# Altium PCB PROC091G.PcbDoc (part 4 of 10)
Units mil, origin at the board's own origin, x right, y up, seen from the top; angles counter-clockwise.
Board outline 4538.11 x 994.94 mil, 8 copper layers (Top Layer, GND1, Sig1, PWR1, PWR2, Sig2, GND2, Bottom Layer), stack 59.155 mil thick; 446 components, 329 nets, 5050 pads, 868 vias.
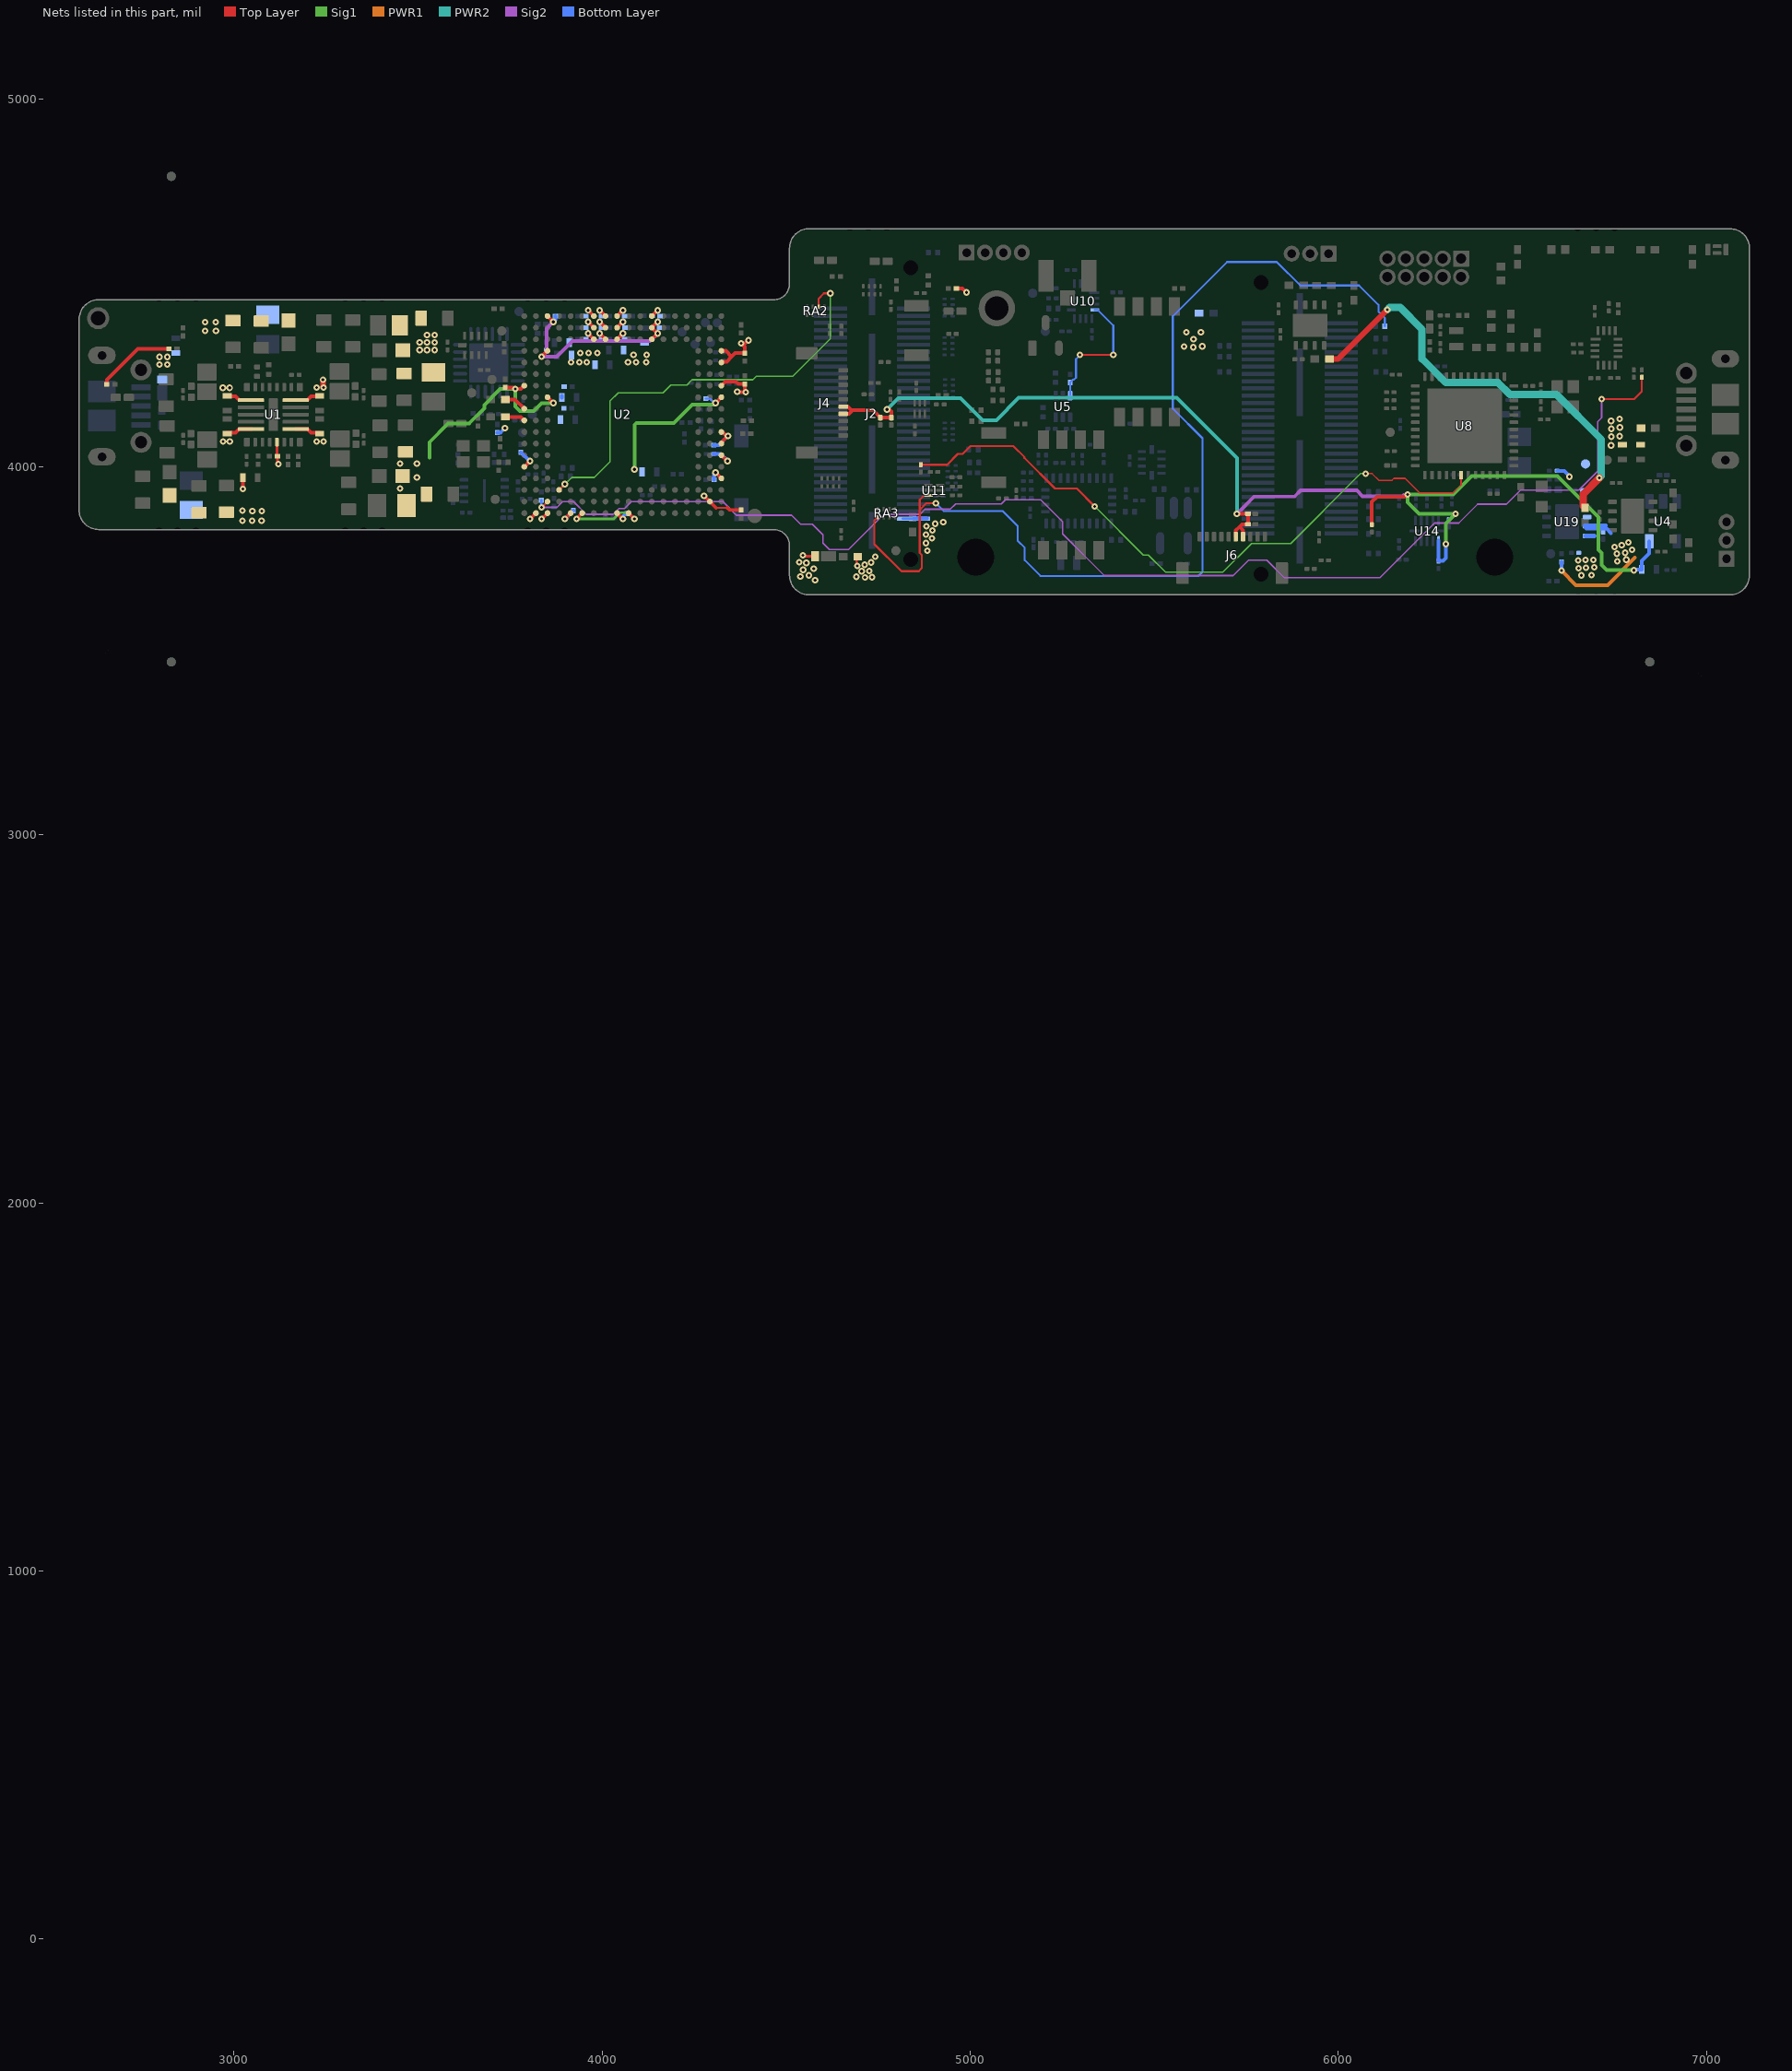
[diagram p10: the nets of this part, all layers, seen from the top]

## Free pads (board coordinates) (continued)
  round 7 on Mech16: 1(2948.71,736.96) 1(2948.71,736.96) 1(2948.71,777.96) 1(2948.71,777.96) 1(2971.71,736.96) 1(2971.71,777.96) 1(3021.71,736.96) 1(3021.71,777.96) 1(3044.71,736.96) 1(3044.71,736.96) 1(3044.71,777.96) 1(3044.71,777.96) 1(3078.65,310.39) 1(3078.65,310.39) 1(3078.65,410.39) 1(3078.65,510.39) 1(3078.65,510.39) 1(3178.65,310.39) 1(3178.65,410.39) 1(3178.65,410.39) 1(3227.52,1910.06) 1(3227.52,1910.06) 1(3227.52,1933.06) 1(3227.52,1983.06) 1(3227.52,2006.06) 1(3227.52,2006.06) 1(3228.65,88.39) 1(3228.65,88.39) 1(3228.65,188.39) 1(3228.65,288.39) 1(3228.65,288.39) 1(3252.65,1637.89) 1(3252.65,1637.89) 1(3252.65,1678.89) 1(3252.65,1678.89) 1(3253.27,1687.42) 1(3253.27,1687.42) 1(3253.27,1728.42) 1(3253.27,1728.42) 1(3253.91,1076.83) 1(3253.91,1076.83) 1(3253.91,1117.83) 1(3253.91,1117.83) 1(3253.91,1126.83) 1(3253.91,1126.83) 1(3253.91,1167.83) 1(3253.91,1167.83) 1(3253.91,1176.83) 1(3253.91,1176.83) 1(3253.91,1217.83) 1(3253.91,1217.83) 1(3253.91,1226.83) 1(3253.91,1226.83) 1(3253.91,1267.83) 1(3253.91,1267.83) 1(3253.91,1276.83) 1(3253.91,1276.83) 1(3253.91,1317.83) 1(3253.91,1317.83) 1(3253.91,1331.83) 1(3253.91,1331.83) 1(3253.91,1372.83) 1(3253.91,1372.83) 1(3253.91,1381.83) 1(3253.91,1381.83) 1(3253.91,1422.83) 1(3253.91,1422.83) 1(3253.91,1486.83) 1(3253.91,1486.83) 1(3253.91,1527.83) 1(3253.91,1527.83) 1(3253.91,1536.83) 1(3253.91,1536.83) 1(3253.91,1577.83) 1(3253.91,1577.83) 1(3253.91,1586.83) 1(3253.91,1586.83) 1(3253.91,1627.83) 1(3253.91,1627.83) 1(3253.91,1026.83) 1(3253.91,1026.83) 1(3253.91,1067.83) 1(3253.91,1067.83) 1(3253.91,1431.83) 1(3253.91,1431.83) 1(3253.91,1472.83) 1(3253.91,1472.83) 1(3268.52,1910.06) 1(3268.52,1910.06) 1(3268.52,1933.06) 1(3268.52,1983.06) 1(3268.52,2006.06) 1(3268.52,2006.06) 1(3275.65,1637.89) 1(3275.65,1678.89) 1(3276.27,1687.42) 1(3276.27,1728.42) 1(3276.91,1076.83) 1(3276.91,1117.83) 1(3276.91,1126.83) 1(3276.91,1167.83) 1(3276.91,1176.83) 1(3276.91,1217.83) 1(3276.91,1226.83) 1(3276.91,1267.83) 1(3276.91,1276.83) 1(3276.91,1317.83) 1(3276.91,1331.83) 1(3276.91,1372.83) 1(3276.91,1381.83) 1(3276.91,1422.83) 1(3276.91,1486.83) 1(3276.91,1527.83) 1(3276.91,1536.83) 1(3276.91,1577.83) 1(3276.91,1586.83) 1(3276.91,1627.83) 1(3276.91,1026.83) 1(3276.91,1067.83) 1(3276.91,1431.83) 1(3276.91,1472.83) 1(3296.75,1733.96) 1(3296.75,1733.96) 1(3296.75,1759.94) 1(3296.75,1827.94) 1(3296.75,1853.92) 1(3296.75,1853.92) 1(3297.01,1910.44) 1(3297.01,1910.44) 1(3297.01,1933.44) 1(3297.01,1983.44) 1(3297.01,2006.44) 1(3297.01,2006.44) 1(3316.37,680.35) 1(3316.37,680.35) 1(3316.37,734.81) 1(3316.37,734.81) 1(3325.65,1637.89) 1(3325.65,1678.89) 1(3326.27,1687.42) 1(3326.27,1728.42) 1(3326.91,1076.83) 1(3326.91,1117.83) 1(3326.91,1126.83) 1(3326.91,1167.83) 1(3326.91,1176.83) 1(3326.91,1217.83) 1(3326.91,1226.83) 1(3326.91,1267.83) 1(3326.91,1276.83) 1(3326.91,1317.83) 1(3326.91,1331.83) 1(3326.91,1372.83) 1(3326.91,1381.83) 1(3326.91,1422.83) 1(3326.91,1486.83) 1(3326.91,1527.83) 1(3326.91,1536.83) 1(3326.91,1577.83) 1(3326.91,1586.83) 1(3326.91,1627.83) 1(3326.91,1026.83) 1(3326.91,1067.83) 1(3326.91,1431.83) 1(3326.91,1472.83) 1(3328.65,88.39) 1(3328.65,188.39) 1(3328.65,188.39) 1(3338.01,1910.44) 1(3338.01,1910.44) 1(3338.01,1933.44) 1(3338.01,1983.44) 1(3338.01,2006.44) 1(3338.01,2006.44) 1(3342.35,680.35) 1(3342.35,734.81) 1(3348.65,1637.89) 1(3348.65,1637.89) 1(3348.65,1678.89) 1(3348.65,1678.89) 1(3349.27,1687.42) 1(3349.27,1687.42) 1(3349.27,1728.42) 1(3349.27,1728.42) 1(3349.91,1076.83) 1(3349.91,1076.83) 1(3349.91,1117.83) 1(3349.91,1117.83) 1(3349.91,1126.83) 1(3349.91,1126.83) 1(3349.91,1167.83) 1(3349.91,1167.83) 1(3349.91,1176.83) 1(3349.91,1176.83) 1(3349.91,1217.83) 1(3349.91,1217.83) 1(3349.91,1226.83) 1(3349.91,1226.83) 1(3349.91,1267.83) 1(3349.91,1267.83) 1(3349.91,1276.83) 1(3349.91,1276.83) 1(3349.91,1317.83) 1(3349.91,1317.83) 1(3349.91,1331.83) 1(3349.91,1331.83) 1(3349.91,1372.83) 1(3349.91,1372.83) 1(3349.91,1381.83) 1(3349.91,1381.83) 1(3349.91,1422.83) 1(3349.91,1422.83) 1(3349.91,1486.83) 1(3349.91,1486.83) 1(3349.91,1527.83) 1(3349.91,1527.83) 1(3349.91,1536.83) 1(3349.91,1536.83) 1(3349.91,1577.83) 1(3349.91,1577.83) 1(3349.91,1586.83) 1(3349.91,1586.83) 1(3349.91,1627.83) 1(3349.91,1627.83) 1(3349.91,1026.83) 1(3349.91,1026.83) 1(3349.91,1067.83) 1(3349.91,1067.83) 1(3349.91,1431.83) 1(3349.91,1431.83) 1(3349.91,1472.83) 1(3349.91,1472.83) 1(3351.22,1733.96) 1(3351.22,1733.96) 1(3351.22,1759.94) 1(3351.22,1827.94) 1(3351.22,1853.92) 1(3351.22,1853.92) 1(3389.82,1421.46) 1(3389.82,1421.46) 1(3389.82,1447.44) 1(3389.82,1515.44) 1(3389.82,1541.42) 1(3389.82,1541.42) 1(3410.35,680.35) 1(3410.35,734.81) 1(3436.33,680.35) 1(3436.33,680.35) 1(3436.33,734.81) 1(3436.33,734.81) 1(3444.28,1421.46) 1(3444.28,1421.46) 1(3444.28,1447.44) 1(3444.28,1515.44) 1(3444.28,1541.42) 1(3444.28,1541.42) 1(3453.4,2001.94) 1(3453.4,2001.94) 1(3453.4,2042.94) 1(3453.4,2042.94) 1(3454.02,1923.94) 1(3454.02,1923.94) 1(3454.02,1964.94) 1(3454.02,1964.94) 1(3476.4,2001.94) 1(3476.4,2042.94) 1(3477.02,1923.94) 1(3477.02,1964.94) 1(3511.28,2264.89) 1(3511.28,2264.89) 1(3511.28,2305.89) 1(3511.28,2305.89) 1(3518.76,1756.44) 1(3518.76,1756.44) 1(3518.76,1779.44) 1(3518.76,1829.44) 1(3518.76,1852.44) 1(3518.76,1852.44) 1(3526.4,2001.94) 1(3526.4,2042.94) 1(3527.02,1923.94) 1(3527.02,1964.94) 1(3531.97,2113.83) 1(3531.97,2113.83) 1(3531.97,2154.83) 1(3531.97,2154.83) 1(3534.28,2264.89) 1(3534.28,2305.89) 1(3549.4,2001.94) 1(3549.4,2001.94) 1(3549.4,2042.94) 1(3549.4,2042.94) 1(3550.02,1923.94) 1(3550.02,1923.94) 1(3550.02,1964.94) 1(3550.02,1964.94) 1(3554.97,2113.83) 1(3554.97,2154.83) 1(3559.76,1756.44) 1(3559.76,1756.44) 1(3559.76,1779.44) 1(3559.76,1829.44) 1(3559.76,1852.44) 1(3559.76,1852.44) 1(3584.28,2264.89) 1(3584.28,2305.89) 1(3586.87,2535.95) 1(3586.87,2535.95) 1(3586.87,2561.93) 1(3586.87,2629.93) 1(3586.87,2655.91) 1(3586.87,2655.91) 1(3587.52,1796.44) 1(3587.52,1796.44) 1(3587.52,1819.44) 1(3587.52,1869.44) 1(3587.52,1892.44) 1(3587.52,1892.44) 1(3604.97,2113.83) 1(3604.97,2154.83) 1(3607.28,2264.89) 1(3607.28,2264.89) 1(3607.28,2305.89) 1(3607.28,2305.89) 1(3627.97,2113.83) 1(3627.97,2113.83) 1(3627.97,2154.83) 1(3627.97,2154.83) 1(3628.52,1796.44) 1(3628.52,1796.44) 1(3628.52,1819.44) 1(3628.52,1869.44) 1(3628.52,1892.44) 1(3628.52,1892.44) 1(3641.33,2535.95) 1(3641.33,2535.95) 1(3641.33,2561.93) 1(3641.33,2629.93) 1(3641.33,2655.91) 1(3641.33,2655.91) 1(3660.65,2692.89) 1(3660.65,2692.89) 1(3660.65,2733.89) 1(3660.65,2733.89) 1(3683.65,2692.89) 1(3683.65,2733.89) 1(3685.16,2766.12) 1(3685.16,2766.12) 1(3685.16,2820.59) 1(3685.16,2820.59) 1(3700.65,2832.89) 1(3700.65,2832.89) 1(3700.65,2873.89) 1(3700.65,2873.89) 1(3702.5,2882.04) 1(3702.5,2882.04) 1(3702.5,2923.04) 1(3702.5,2923.04) 1(3702.5,2932.04) 1(3702.5,2932.04) 1(3702.5,2973.04) 1(3702.5,2973.04) 1(3702.5,2982.04) 1(3702.5,2982.04) 1(3702.5,3023.04) 1(3702.5,3023.04) 1(3702.5,3082.04) 1(3702.5,3082.04) 1(3702.5,3123.04) 1(3702.5,3123.04) 1(3705.65,3132.89) 1(3705.65,3132.89) 1(3705.65,3173.89) 1(3705.65,3173.89) 1(3705.65,3187.89) 1(3705.65,3187.89) 1(3705.65,3228.89) 1(3705.65,3228.89) 1(3711.14,2766.12) 1(3711.14,2820.59) 1(3723.65,2832.89) 1(3723.65,2873.89) 1(3725.5,2882.04) 1(3725.5,2923.04) 1(3725.5,2932.04) 1(3725.5,2973.04) 1(3725.5,2982.04) 1(3725.5,3023.04) 1(3725.5,3082.04) 1(3725.5,3123.04) 1(3727.02,1435.44) 1(3727.02,1435.44) 1(3727.02,1469.44) 1(3727.02,1549.44) 1(3727.02,1583.44) 1(3727.02,1583.44) 1(3728.65,88.39) 1(3728.65,88.39) 1(3728.65,288.39) 1(3728.65,288.39) 1(3728.65,3132.89) 1(3728.65,3173.89) 1(3728.65,3187.89) 1(3728.65,3228.89) 1(3733.65,2692.89) 1(3733.65,2733.89) 1(3745.29,729.24) 1(3745.29,729.24) 1(3745.29,760.95) 1(3745.29,879.93) 1(3745.29,911.64) 1(3745.29,911.64) 1(3756.65,2692.89) 1(3756.65,2692.89) 1(3756.65,2733.89) 1(3756.65,2733.89) 1(3767.02,1435.44) 1(3767.02,1435.44) 1(3767.02,1583.44) 1(3767.02,1583.44) 1(3770.53,1331.8) 1(3770.53,1331.8) 1(3770.53,1427.08) 1(3770.53,1427.08) 1(3773.02,3354.94) 1(3773.02,3354.94) 1(3773.02,3395.94) 1(3773.02,3395.94) 1(3773.65,2832.89) 1(3773.65,2873.89) 1(3775.5,2882.04) 1(3775.5,2923.04) 1(3775.5,2932.04) 1(3775.5,2973.04) 1(3775.5,2982.04) 1(3775.5,3023.04) 1(3775.5,3082.04) 1(3775.5,3123.04) 1(3778.65,3132.89) 1(3778.65,3173.89) 1(3778.65,3187.89) 1(3778.65,3228.89) 1(3779.14,2766.12) 1(3779.14,2820.59) 1(3780.01,1116.9) 1(3780.01,1116.9) 1(3780.01,1152.33) 1(3780.01,1270.44) 1(3780.01,1305.87) 1(3780.01,1305.87) 1(3796.02,3354.94) 1(3796.02,3395.94) 1(3796.65,2832.89) 1(3796.65,2832.89) 1(3796.65,2873.89) 1(3796.65,2873.89) 1(3798.5,2882.04) 1(3798.5,2882.04) 1(3798.5,2923.04) 1(3798.5,2923.04) 1(3798.5,2932.04) 1(3798.5,2932.04) 1(3798.5,2973.04) 1(3798.5,2973.04) 1(3798.5,2982.04) 1(3798.5,2982.04) 1(3798.5,3023.04) 1(3798.5,3023.04) 1(3798.5,3082.04) 1(3798.5,3082.04) 1(3798.5,3123.04) 1(3798.5,3123.04) 1(3801.65,3132.89) 1(3801.65,3132.89) 1(3801.65,3173.89) 1(3801.65,3173.89) 1(3801.65,3187.89) 1(3801.65,3187.89) 1(3801.65,3228.89) 1(3801.65,3228.89) 1(3805.13,2766.12) 1(3805.13,2766.12) 1(3805.13,2820.59) 1(3805.13,2820.59) 1(3805.96,1331.8) 1(3805.96,1427.08) 1(3807.02,1435.44) 1(3807.02,1435.44) 1(3807.02,1469.44) 1(3807.02,1549.44) 1(3807.02,1583.44) 1(3807.02,1583.44) 1(3809.81,931.38) 1(3809.81,931.38) 1(3809.81,971.38) 1(3809.81,971.38) 1(3809.81,1011.38) 1(3809.81,1011.38) 1(3820.79,1542.03) 1(3820.79,1542.03) 1(3820.79,1596.5) 1(3820.79,1596.5) 1(3831.38,2523.4) 1(3831.38,2523.4) 1(3831.38,2549.39) 1(3831.38,2617.39) 1(3831.38,2643.37) 1(3831.38,2643.37) 1(3833.14,2408.52) 1(3833.14,2408.52) 1(3833.14,2484.02) 1(3833.14,2484.02) 1(3833.83,2407.82) 1(3833.83,2407.82) 1(3843.81,931.38) 1(3843.81,1011.38) 1(3846.02,3354.94) 1(3846.02,3395.94) 1(3846.45,2653.4) 1(3846.45,2653.4) 1(3846.45,2679.39) 1(3846.45,2747.39) 1(3846.45,2773.37) 1(3846.45,2773.37) 1(3846.78,1542.03) 1(3846.78,1596.5) 1(3868.74,729.24) 1(3868.74,729.24) 1(3868.74,760.95) 1(3868.74,879.93) 1(3868.74,911.64) 1(3868.74,911.64) 1(3869.02,3354.94) 1(3869.02,3354.94) 1(3869.02,3395.94) 1(3869.02,3395.94) 1(3870.74,2407.82) 1(3870.74,2484.02) 1(3875.29,1116.9) 1(3875.29,1116.9) 1(3875.29,1152.33) 1(3875.29,1270.44) 1(3875.29,1305.87) 1(3875.29,1305.87) 1(3878.02,759.44) 1(3878.02,759.44) 1(3878.02,793.44) 1(3878.02,873.44) 1(3878.02,907.44) 1(3878.02,907.44) 1(3878.65,310.39) 1(3878.65,310.39) 1(3878.65,510.39) 1(3878.65,510.39) 1(3885.85,2523.4) 1(3885.85,2523.4) 1(3885.85,2549.39) 1(3885.85,2617.39) 1(3885.85,2643.37) 1(3885.85,2643.37) 1(3893.65,310.39) 1(3893.65,310.39) 1(3893.65,410.39) 1(3893.65,510.39) 1(3893.65,510.39) 1(3900.91,2653.4) 1(3900.91,2653.4) 1(3900.91,2679.39) 1(3900.91,2747.39) 1(3900.91,2773.37) 1(3900.91,2773.37) 1(3910.02,2502.94) 1(3910.02,2502.94) 1(3910.02,2543.94) 1(3910.02,2543.94) 1(3910.93,2615.57) 1(3910.93,2615.57) 1(3910.93,2638.57) 1(3910.93,2688.57) 1(3910.93,2711.57) 1(3910.93,2711.57) 1(3911.02,1273.94) 1(3911.02,1273.94) 1(3911.02,1314.94) 1(3911.02,1314.94) 1(3914.78,1542.03) 1(3914.78,1596.5) 1(3914.81,2752.07) 1(3914.81,2752.07) 1(3914.81,2793.07) 1(3914.81,2793.07) 1(3915.93,3359.57) 1(3915.93,3359.57) 1(3915.93,3382.57) 1(3915.93,3432.57) 1(3915.93,3455.57) 1(3915.93,3455.57) 1(3918.02,759.44) 1(3918.02,759.44) 1(3918.02,907.44) 1(3918.02,907.44) 1(3923.81,931.38) 1(3923.81,1011.38) 1(3924.07,1331.8) 1(3924.07,1427.08) 1(3930.74,2407.82) 1(3930.74,2484.02) 1(3933.02,2502.94) 1(3933.02,2543.94) 1(3934.02,1273.94) 1(3934.02,1314.94) 1(3937.81,2752.07) 1(3937.81,2793.07) 1(3940.76,1542.03) 1(3940.76,1542.03) 1(3940.76,1596.5) 1(3940.76,1596.5) 1(3951.93,2615.57) 1(3951.93,2615.57) 1(3951.93,2638.57) 1(3951.93,2688.57) 1(3951.93,2711.57) 1(3951.93,2711.57) 1(3956.93,3359.57) 1(3956.93,3359.57) 1(3956.93,3382.57) 1(3956.93,3432.57) 1(3956.93,3455.57) 1(3956.93,3455.57) 1(3957.81,931.38) 1(3957.81,931.38) 1(3957.81,971.38) 1(3957.81,971.38) 1(3957.81,1011.38) 1(3957.81,1011.38) 1(3958.02,759.44) 1(3958.02,759.44) 1(3958.02,793.44) 1(3958.02,873.44) 1(3958.02,907.44) 1(3958.02,907.44) 1(3959.51,1331.8) 1(3959.51,1331.8) 1(3959.51,1427.08) 1(3959.51,1427.08) 1(3962.08,2615.57) 1(3962.08,2615.57) 1(3962.08,2638.57) 1(3962.08,2688.57) 1(3962.08,2711.57) 1(3962.08,2711.57) 1(3965.93,3359.57) 1(3965.93,3359.57) 1(3965.93,3382.57) 1(3965.93,3432.57) 1(3965.93,3455.57) 1(3965.93,3455.57) 1(3967.64,2407.82) 1(3967.64,2407.82) 1(3968.34,2408.52) 1(3968.34,2408.52) 1(3968.34,2484.02) 1(3968.34,2484.02) 1(3969.54,586.85) 1(3969.54,586.85) 1(3969.54,608.11) 1(3969.54,698.66) 1(3969.54,719.92) 1(3969.54,719.92) 1(3983.02,2502.94) 1(3983.02,2543.94) 1(3983.15,2376.76) 1(3983.15,2376.76) 1(3983.15,2399.76) 1(3983.15,2449.76) 1(3983.15,2472.76) 1(3983.15,2472.76) 1(3984.02,1273.94) 1(3984.02,1314.94) 1(3987.81,2752.07) 1(3987.81,2793.07) 1(3993.65,310.39) 1(3993.65,410.39) 1(3993.65,410.39) 1(4003.08,2615.57) 1(4003.08,2615.57) 1(4003.08,2638.57) 1(4003.08,2688.57) 1(4003.08,2711.57) 1(4003.08,2711.57) 1(4006.02,2502.94) 1(4006.02,2502.94) 1(4006.02,2543.94) 1(4006.02,2543.94) 1(4006.93,3359.57) 1(4006.93,3359.57) 1(4006.93,3382.57) 1(4006.93,3432.57) 1(4006.93,3455.57) 1(4006.93,3455.57) 1(4007.02,1273.94) 1(4007.02,1273.94) 1(4007.02,1314.94) 1(4007.02,1314.94) 1(4010.81,2752.07) 1(4010.81,2752.07) 1(4010.81,2793.07) 1(4010.81,2793.07) 1(4011.27,545.12) 1(4011.27,545.12) 1(4011.27,761.65) 1(4011.27,761.65) 1(4012.08,2615.57) 1(4012.08,2615.57) 1(4012.08,2638.57) 1(4012.08,2688.57) 1(4012.08,2711.57) 1(4012.08,2711.57) 1(4015.93,3359.57) 1(4015.93,3359.57) 1(4015.93,3382.57) 1(4015.93,3432.57) 1(4015.93,3455.57) 1(4015.93,3455.57) 1(4024.15,2376.76) 1(4024.15,2376.76) 1(4024.15,2399.76) 1(4024.15,2449.76) 1(4024.15,2472.76) 1(4024.15,2472.76) 1(4025.15,1282.63) 1(4025.15,1306.25) 1(4036.02,2250.94) 1(4036.02,2250.94) 1(4036.02,2291.94) 1(4036.02,2291.94) 1(4053.08,2615.57) 1(4053.08,2615.57) 1(4053.08,2638.57) 1(4053.08,2688.57) 1(4053.08,2711.57) 1(4053.08,2711.57) 1(4055.93,3464.57) 1(4055.93,3464.57) 1(4055.93,3487.57) 1(4055.93,3537.57) 1(4055.93,3560.57) 1(4055.93,3560.57) 1(4056.93,3359.57) 1(4056.93,3359.57) 1(4056.93,3382.57) 1(4056.93,3432.57) 1(4056.93,3455.57) 1(4056.93,3455.57) 1(4059.02,2250.94) 1(4059.02,2291.94) 1(4063.08,2615.57) 1(4063.08,2615.57) 1(4063.08,2638.57) 1(4063.08,2688.57) 1(4063.08,2711.57) 1(4063.08,2711.57) 1(4063.43,2752.07) 1(4063.43,2752.07) 1(4063.43,2793.07) 1(4063.43,2793.07) 1(4065.93,3359.57) 1(4065.93,3359.57) 1(4065.93,3382.57) 1(4065.93,3432.57) 1(4065.93,3455.57) 1(4065.93,3455.57) 1(4077.8,545.12) 1(4077.8,545.12) 1(4077.8,761.65) 1(4077.8,761.65) 1(4086.43,2752.07) 1(4086.43,2793.07) 1(4096.93,3464.57) 1(4096.93,3464.57) 1(4096.93,3487.57) 1(4096.93,3537.57) 1(4096.93,3560.57) 1(4096.93,3560.57) 1(4104.08,2615.57) 1(4104.08,2615.57) 1(4104.08,2638.57) 1(4104.08,2688.57) 1(4104.08,2711.57) 1(4104.08,2711.57) 1(4106.93,3359.57) 1(4106.93,3359.57) 1(4106.93,3382.57) 1(4106.93,3432.57) 1(4106.93,3455.57) 1(4106.93,3455.57) 1(4109.02,2250.94) 1(4109.02,2291.94) 1(4110.93,3464.57) 1(4110.93,3464.57) 1(4110.93,3487.57) 1(4110.93,3537.57) 1(4110.93,3560.57) 1(4110.93,3560.57) 1(4114.08,2615.57) 1(4114.08,2615.57) 1(4114.08,2638.57) 1(4114.08,2688.57) 1(4114.08,2711.57) 1(4114.08,2711.57) 1(4115.93,3359.57) 1(4115.93,3359.57) 1(4115.93,3382.57) 1(4115.93,3432.57) 1(4115.93,3455.57) 1(4115.93,3455.57) 1(4132.02,2250.94) 1(4132.02,2250.94) 1(4132.02,2291.94) 1(4132.02,2291.94) 1(4136.43,2752.07) 1(4136.43,2793.07) 1(4151.93,3464.57) 1(4151.93,3464.57) 1(4151.93,3487.57) 1(4151.93,3537.57) 1(4151.93,3560.57) 1(4151.93,3560.57) 1(4155.08,2615.57) 1(4155.08,2615.57) 1(4155.08,2638.57) 1(4155.08,2688.57) 1(4155.08,2711.57) 1(4155.08,2711.57) 1(4156.93,3359.57) 1(4156.93,3359.57) 1(4156.93,3382.57) 1(4156.93,3432.57) 1(4156.93,3455.57) 1(4156.93,3455.57) 1(4159.43,2752.07) 1(4159.43,2752.07) 1(4159.43,2793.07) 1(4159.43,2793.07) 1(4165.08,2615.57) 1(4165.08,2615.57) 1(4165.08,2638.57) 1(4165.08,2688.57) 1(4165.08,2711.57) 1(4165.08,2711.57) 1(4169.16,3357.58) 1(4169.16,3357.58) 1(4169.16,3383.57) 1(4169.16,3451.57) 1(4169.16,3477.55) 1(4169.16,3477.55) 1(4184.02,993.94) 1(4184.02,993.94) 1(4184.02,1034.94) 1(4184.02,1034.94) 1(4186.07,545.12) 1(4186.07,545.12) 1(4186.07,608.11) 1(4186.07,698.66) 1(4186.07,761.65) 1(4186.07,761.65) 1(4196.02,770.44) 1(4196.02,770.44) 1(4196.02,804.44) 1(4196.02,884.44) 1(4196.02,918.44) 1(4196.02,918.44) 1(4206.08,2615.57) 1(4206.08,2615.57) 1(4206.08,2638.57) 1(4206.08,2688.57) 1(4206.08,2711.57) 1(4206.08,2711.57) 1(4207.02,993.94) 1(4207.02,1034.94) 1(4216.08,2615.57) 1(4216.08,2615.57) 1(4216.08,2638.57) 1(4216.08,2688.57) 1(4216.08,2711.57) 1(4216.08,2711.57) 1(4222.34,2754.84) 1(4222.34,2754.84) 1(4222.34,2795.84) 1(4222.34,2795.84) 1(4223.63,3357.58) 1(4223.63,3357.58) 1(4223.63,3383.57) 1(4223.63,3451.57) 1(4223.63,3477.55) 1(4223.63,3477.55) 1(4232.74,3359.57) 1(4232.74,3359.57) 1(4232.74,3382.57) 1(4232.74,3432.57) 1(4232.74,3455.57) 1(4232.74,3455.57) 1(4236.02,770.44) 1(4236.02,770.44) 1(4236.02,918.44) 1(4236.02,918.44) 1(4241.65,1714.74) 1(4241.65,1714.74) 1(4241.65,1755.74) 1(4241.65,1755.74) 1(4245.34,2754.84) 1(4245.34,2795.84) 1(4248.65,1536.74) 1(4248.65,1536.74) 1(4248.65,1577.74) 1(4248.65,1577.74) 1(4257.02,993.94) 1(4257.02,1034.94) 1(4257.08,2615.57) 1(4257.08,2615.57) 1(4257.08,2638.57) 1(4257.08,2688.57) 1(4257.08,2711.57) 1(4257.08,2711.57) 1(4264.65,1714.74) 1(4264.65,1755.74) 1(4265.08,2615.57) 1(4265.08,2615.57) 1(4265.08,2638.57) 1(4265.08,2688.57) 1(4265.08,2711.57) 1(4265.08,2711.57) 1(4271.65,1536.74) 1(4271.65,1577.74) 1(4273.74,3359.57) 1(4273.74,3359.57) 1(4273.74,3382.57) 1(4273.74,3432.57) 1(4273.74,3455.57) 1(4273.74,3455.57) 1(4276.02,770.44) 1(4276.02,770.44) 1(4276.02,804.44) 1(4276.02,884.44) 1(4276.02,918.44) 1(4276.02,918.44) 1(4280.02,993.94) 1(4280.02,993.94) 1(4280.02,1034.94) 1(4280.02,1034.94) 1(4285.29,753.24) 1(4285.29,753.24) 1(4285.29,784.95) 1(4285.29,903.93) 1(4285.29,935.64) 1(4285.29,935.64) 1(4285.93,3359.57) 1(4285.93,3359.57) 1(4285.93,3382.57) 1(4285.93,3432.57) 1(4285.93,3455.57) 1(4285.93,3455.57) 1(4295.34,2754.84) 1(4295.34,2795.84) 1(4297.15,1592.24) 1(4297.15,1592.24) 1(4297.15,1615.24) 1(4297.15,1665.24) 1(4297.15,1688.24) 1(4297.15,1688.24) 1(4306.08,2615.57) 1(4306.08,2615.57) 1(4306.08,2638.57) 1(4306.08,2688.57) 1(4306.08,2711.57) 1(4306.08,2711.57) 1(4314.65,1714.74) 1(4314.65,1755.74) 1(4318.34,2754.84) 1(4318.34,2754.84) 1(4318.34,2795.84) 1(4318.34,2795.84) 1(4321.65,1536.74) 1(4321.65,1577.74) 1(4325.65,2522.89) 1(4325.65,2522.89) 1(4325.65,2563.89) 1(4325.65,2563.89) 1(4325.65,2572.89) 1(4325.65,2572.89) 1(4325.65,2613.89) 1(4325.65,2613.89) 1(4326.93,3359.57) 1(4326.93,3359.57) 1(4326.93,3382.57) 1(4326.93,3432.57) 1(4326.93,3455.57) 1(4326.93,3455.57) 1(4335.93,3359.57) 1(4335.93,3359.57) 1(4335.93,3382.57) 1(4335.93,3432.57) 1(4335.93,3455.57) 1(4335.93,3455.57) 1(4337.65,1714.74) 1(4337.65,1714.74) 1(4337.65,1755.74) 1(4337.65,1755.74) 1(4338.15,1592.24) 1(4338.15,1592.24) 1(4338.15,1615.24) 1(4338.15,1665.24) 1(4338.15,1688.24) 1(4338.15,1688.24) 1(4344.65,1536.74) 1(4344.65,1536.74) 1(4344.65,1577.74) 1(4344.65,1577.74) 1(4348.65,2522.89) 1(4348.65,2563.89) 1(4348.65,2572.89) 1(4348.65,2613.89) 1(4360.93,3084.57) 1(4360.93,3084.57) 1(4360.93,3107.57) 1(4360.93,3157.57) 1(4360.93,3180.57) 1(4360.93,3180.57) 1(4362.15,3229.39) 1(4362.15,3229.39) 1(4362.15,3252.39) 1(4362.15,3302.39) 1(4362.15,3325.39) 1(4362.15,3325.39) 1(4376.93,3359.57) 1(4376.93,3359.57) 1(4376.93,3382.57) 1(4376.93,3432.57) 1(4376.93,3455.57) 1(4376.93,3455.57) 1(4380.36,2898.14) 1(4380.36,2898.14) 1(4380.36,2952.61) 1(4380.36,2952.61) 1(4382.34,2964.84) 1(4382.34,2964.84) 1(4382.34,3005.84) 1(4382.34,3005.84) 1(4382.34,3014.84) 1(4382.34,3014.84) 1(4382.34,3055.84) 1(4382.34,3055.84) 1(4398.65,2522.89) 1(4398.65,2563.89) 1(4398.65,2572.89) 1(4398.65,2613.89) 1(4401.93,3084.57) 1(4401.93,3084.57) 1(4401.93,3107.57) 1(4401.93,3157.57) 1(4401.93,3180.57) 1(4401.93,3180.57) 1(4402.57,2847.89) 1(4402.57,2847.89) 1(4402.57,2888.89) 1(4402.57,2888.89) 1(4403.15,3229.39) 1(4403.15,3229.39) 1(4403.15,3252.39) 1(4403.15,3302.39) 1(4403.15,3325.39) 1(4403.15,3325.39) 1(4405.34,2964.84) 1(4405.34,3005.84) 1(4405.34,3014.84) 1(4405.34,3055.84) 1(4406.34,2898.14) 1(4406.34,2952.61) 1(4408.74,753.24) 1(4408.74,753.24) 1(4408.74,784.95) 1(4408.74,903.93) 1(4408.74,935.64) 1(4408.74,935.64) 1(4413,3084.97) 1(4413,3084.97) 1(4413,3107.97) 1(4413,3157.97) 1(4413,3180.97) 1(4413,3180.97) 1(4421.65,2522.89) 1(4421.65,2522.89) 1(4421.65,2563.89) 1(4421.65,2563.89) 1(4421.65,2572.89) 1(4421.65,2572.89) 1(4421.65,2613.89) 1(4421.65,2613.89) 1(4425.57,2847.89) 1(4425.57,2888.89) 1(4430.65,2522.89) 1(4430.65,2522.89) 1(4430.65,2563.89) 1(4430.65,2563.89) 1(4430.65,2572.89) 1(4430.65,2572.89) 1(4430.65,2613.89) 1(4430.65,2613.89) 1(4453.65,2522.89) 1(4453.65,2563.89) 1(4453.65,2572.89) 1(4453.65,2613.89) 1(4454,3084.97) 1(4454,3084.97) 1(4454,3107.97) 1(4454,3157.97) 1(4454,3180.97) 1(4454,3180.97) 1(4455.34,2964.84) 1(4455.34,3005.84) 1(4455.34,3014.84) 1(4455.34,3055.84) 1(4466.23,3082.99) 1(4466.23,3082.99) 1(4466.23,3108.97) 1(4466.23,3176.97) 1(4466.23,3202.95) 1(4466.23,3202.95) 1(4474.34,2898.14) 1(4474.34,2952.61) 1(4475.57,2847.89) 1(4475.57,2888.89) 1(4478.34,2964.84) 1(4478.34,2964.84) 1(4478.34,3005.84) 1(4478.34,3005.84) 1(4478.34,3014.84) 1(4478.34,3014.84) 1(4478.34,3055.84) 1(4478.34,3055.84) 1(4498.57,2847.89) 1(4498.57,2847.89) 1(4498.57,2888.89) 1(4498.57,2888.89) 1(4500.32,2898.14) 1(4500.32,2898.14) 1(4500.32,2952.61) 1(4500.32,2952.61) 1(4503.65,2522.89) 1(4503.65,2563.89) 1(4503.65,2572.89) 1(4503.65,2613.89) 1(4520.7,3082.99) 1(4520.7,3082.99) 1(4520.7,3108.97) 1(4520.7,3176.97) 1(4520.7,3202.95) 1(4520.7,3202.95) 1(4526.65,2522.89) 1(4526.65,2522.89) 1(4526.65,2563.89) 1(4526.65,2563.89) 1(4526.65,2572.89) 1(4526.65,2572.89) 1(4526.65,2613.89) 1(4526.65,2613.89) 1(4533,3089.97) 1(4533,3089.97) 1(4533,3112.97) 1(4533,3162.97) 1(4533,3185.97) 1(4533,3185.97) 1(4539.02,792.44) 1(4539.02,792.44) 1(4539.02,832.44) 1(4539.02,832.44) 1(4539.02,872.44) 1(4539.02,872.44) 1(4560.65,2522.89) 1(4560.65,2522.89) 1(4560.65,2563.89) 1(4560.65,2563.89) 1(4560.65,2572.89) 1(4560.65,2572.89) 1(4560.65,2613.89) 1(4560.65,2613.89) 1(4573.02,792.44) 1(4573.02,872.44) 1(4574,3089.97) 1(4574,3089.97) 1(4574,3112.97) 1(4574,3162.97) 1(4574,3185.97) 1(4574,3185.97) 1(4583.65,2522.89) 1(4583.65,2563.89) 1(4583.65,2572.89) 1(4583.65,2613.89) 1(4633.65,2522.89) 1(4633.65,2563.89) 1(4633.65,2572.89) 1(4633.65,2613.89) 1(4653.02,792.44) 1(4653.02,872.44) 1(4656.65,2522.89) 1(4656.65,2522.89) 1(4656.65,2563.89) 1(4656.65,2563.89) 1(4656.65,2572.89) 1(4656.65,2572.89) 1(4656.65,2613.89) 1(4656.65,2613.89) 1(4682.52,1054.44) 1(4682.52,1054.44) 1(4682.52,1077.44) 1(4682.52,1127.44) 1(4682.52,1150.44) 1(4682.52,1150.44) 1(4687.02,792.44) 1(4687.02,792.44) 1(4687.02,832.44) 1(4687.02,832.44) 1(4687.02,872.44) 1(4687.02,872.44) 1(4693.65,310.39) 1(4693.65,310.39) 1(4693.65,510.39) 1(4693.65,510.39) 1(4723.52,1054.44) 1(4723.52,1054.44) 1(4723.52,1077.44) 1(4723.52,1127.44) 1(4723.52,1150.44) 1(4723.52,1150.44) 1(4764.75,635.91) 1(4764.75,635.91) 1(4764.75,657.17) 1(4764.75,747.72) 1(4764.75,768.98) 1(4764.75,768.98) 1(4806.48,594.17) 1(4806.48,594.17) 1(4806.48,810.71) 1(4806.48,810.71) 1(4820.02,1067.44) 1(4820.02,1067.44) 1(4820.02,1107.44) 1(4820.02,1107.44) 1(4820.02,1147.44) 1(4820.02,1147.44) 1(4828.82,1166.72) 1(4828.82,1166.72) 1(4828.82,1290.16) 1(4828.82,1290.16) 1(4854.02,1067.44) 1(4854.02,1147.44) 1(4860.53,1166.72) 1(4860.53,1290.16) 1(4873.02,594.17) 1(4873.02,594.17) 1(4873.02,810.71) 1(4873.02,810.71) 1(4934.02,1067.44) 1(4934.02,1147.44) 1(4938.28,3995.89) 1(4938.28,3995.89) 1(4938.28,4036.89) 1(4938.28,4036.89) 1(4938.28,4046.89) 1(4938.28,4046.89) 1(4938.28,4087.89) 1(4938.28,4087.89) 1(4959.22,1672.82) 1(4959.22,1672.82) 1(4959.22,1713.82) 1(4959.22,1713.82) 1(4961.28,3995.89) 1(4961.28,4036.89) 1(4961.28,4046.89) 1(4961.28,4087.89) 1(4968.02,1067.44) 1(4968.02,1067.44) 1(4968.02,1107.44) 1(4968.02,1107.44) 1(4968.02,1147.44) 1(4968.02,1147.44) 1(4979.51,1166.72) 1(4979.51,1290.16) 1(4981.29,594.17) 1(4981.29,594.17) 1(4981.29,657.17) 1(4981.29,747.72) 1(4981.29,810.71) 1(4981.29,810.71) 1(4982.22,1672.82) 1(4982.22,1713.82) 1(4990.02,1062.94) 1(4990.02,1062.94) 1(4990.02,1103.94) 1(4990.02,1103.94) 1(5011.22,1166.72) 1(5011.22,1166.72) 1(5011.22,1290.16) 1(5011.22,1290.16) 1(5011.28,3995.89) 1(5011.28,4036.89) 1(5011.28,4046.89) 1(5011.28,4087.89) 1(5013.02,1062.94) 1(5013.02,1103.94) 1(5014.52,-142.56) 1(5014.52,-142.56) 1(5014.52,124.44) 1(5023.51,-142.56) 1(5032.22,1672.82) 1(5032.22,1713.82) 1(5034.28,3995.89) 1(5034.28,3995.89) 1(5034.28,4036.89) 1(5034.28,4036.89) 1(5034.28,4046.89) 1(5034.28,4046.89) 1(5034.28,4087.89) 1(5034.28,4087.89) 1(5041.01,148.9) 1(5041.01,148.9) 1(5041.01,184.33) 1(5041.01,302.44) 1(5041.01,337.87) 1(5041.01,337.87) 1(5055.22,1672.82) 1(5055.22,1672.82) 1(5055.22,1713.82) 1(5055.22,1713.82) 1(5060.29,644.24) 1(5060.29,644.24) 1(5060.29,675.95) 1(5060.29,794.93) 1(5060.29,826.64) 1(5060.29,826.64) 1(5063.02,1062.94) 1(5063.02,1103.94) 1(5079.87,1605.34) 1(5079.87,1605.34) 1(5079.87,1646.34) 1(5079.87,1646.34) 1(5086.02,1062.94) 1(5086.02,1062.94) 1(5086.02,1103.94) 1(5086.02,1103.94) 1(5102.87,1605.34) 1(5102.87,1646.34) 1(5136.29,148.9) 1(5136.29,148.9) 1(5136.29,184.33) 1(5136.29,302.44) 1(5136.29,337.87) 1(5136.29,337.87) 1(5152.87,1605.34) 1(5152.87,1646.34) 1(5162.52,-142.56) 1(5171.52,-142.56) 1(5171.52,-142.56) 1(5171.52,124.44) 1(5175.87,1605.34) 1(5175.87,1605.34) 1(5175.87,1646.34) 1(5175.87,1646.34) 1(5178.52,3554.44) 1(5178.52,3554.44) 1(5178.52,3577.44) 1(5178.52,3627.44) 1(5178.52,3650.44) 1(5178.52,3650.44) 1(5182.52,559.44) 1(5183.74,644.24) 1(5183.74,644.24) 1(5183.74,675.95) 1(5183.74,794.93) 1(5183.74,826.64) 1(5183.74,826.64) 1(5208.91,3807.54) 1(5208.91,3807.54) 1(5208.91,3844.44) 1(5208.91,3904.44) 1(5208.91,3941.34) 1(5208.91,3941.34) 1(5209.61,3806.84) 1(5209.61,3806.84) 1(5209.61,3942.04) 1(5209.61,3942.04) 1(5219.52,3554.44) 1(5219.52,3554.44) 1(5219.52,3577.44) 1(5219.52,3627.44) 1(5219.52,3650.44) 1(5219.52,3650.44) 1(5226.26,3553.85) 1(5226.26,3553.85) 1(5226.26,3576.85) 1(5226.26,3626.85) 1(5226.26,3649.85) 1(5226.26,3649.85) 1(5267.26,3553.85) 1(5267.26,3553.85) 1(5267.26,3576.85) 1(5267.26,3626.85) 1(5267.26,3649.85) 1(5267.26,3649.85) 1(5285.11,3806.84) 1(5285.11,3806.84) 1(5285.11,3844.44) 1(5285.11,3904.44) 1(5285.11,3942.04) 1(5285.11,3942.04) 1(5287.52,559.44) 1(5410.44,550.63) 1(5410.44,574.25) 1(5676.81,1172.44)
  round 4 on Mech16: 1(3024.91,3564.33) 1(5190.26,3564.33)
  round 4.02 on Mech16: 1(3024.91,3564.33) 1(5190.26,3564.33)
  round 9.84 on Mech16: 1(3038.29,315.9) 1(3046.64,122.44) 1(3046.64,320.19) 1(3046.64,520.05) 1(3048.14,315.9) 1(3056.49,122.44) 1(3056.49,320.19) 1(3056.49,520.05) 1(3188.29,93.9) 1(3198.14,93.9) 1(3704.36,1009.84) 1(3714.2,1009.84) 1(3853.29,315.9) 1(3863.14,315.9) 1(4303.92,2900.14) 1(4313.76,2900.14) 1(4441.36,2375.71) 1(4441.36,2395.39) 1(4441.36,2454.45) 1(4441.36,2415.08) 1(4441.36,2434.76) 1(4476.8,2375.71) 1(4476.8,2395.39) 1(4476.8,2454.45) 1(4476.8,2415.08) 1(4476.8,2434.76) 1(4499.67,1278.85) 1(4499.67,1298.54) 1(4499.67,1239.48) 1(4499.67,1259.17) 1(4499.67,1318.22) 1(4535.1,1278.85) 1(4535.1,1298.54) 1(4535.1,1239.48) 1(4535.1,1259.17) 1(4535.1,1318.22) 1(4608.69,2415.08) 1(4608.69,2434.76) 1(4608.69,2375.71) 1(4608.69,2395.39) 1(4608.69,2454.45) 1(4644.12,2415.08) 1(4644.12,2434.76) 1(4644.12,2375.71) 1(4644.12,2395.39) 1(4644.12,2454.45) 1(4666.99,1239.48) 1(4666.99,1259.17) 1(4666.99,1278.85) 1(4666.99,1298.54) 1(4666.99,1318.22) 1(4702.43,1239.48) 1(4702.43,1259.17) 1(4702.43,1278.85) 1(4702.43,1298.54) 1(4702.43,1318.22) 1(4744.1,609.99) 1(4753.94,609.99) 1(4866.1,609.99) 1(4875.94,609.99) 1(5000.71,1855.93) 1(5000.71,1891.36) 1(5000.71,2023.25) 1(5000.71,2058.69) 1(5020.39,1855.93) 1(5020.39,1891.36) 1(5020.39,2023.25) 1(5020.39,2058.69) 1(5040.08,1855.93) 1(5040.08,1891.36) 1(5040.08,2023.25) 1(5040.08,2058.69) 1(5059.76,1855.93) 1(5059.76,1891.36) 1(5059.76,2023.25) 1(5059.76,2058.69) 1(5079.45,1855.93) 1(5079.45,1891.36) 1(5079.45,2023.25) 1(5079.45,2058.69)
  round 3.9 on Mech16: 1(3332.07,773.62) 1(3332.07,801.21) 1(3332.07,874.01) 1(3332.07,901.61) 1(3349.83,773.62) 1(3349.83,801.21) 1(3349.83,874.01) 1(3349.83,901.61) 1(3369.47,773.62) 1(3369.47,801.21) 1(3369.47,874.01) 1(3369.47,901.61) 1(3387.23,773.62) 1(3387.23,801.21) 1(3387.23,874.01) 1(3387.23,901.61) 1(3403.74,1569.45) 1(3403.74,1597.04) 1(3403.74,1669.84) 1(3403.74,1697.44) 1(3406.87,773.62) 1(3406.87,801.21) 1(3406.87,874.01) 1(3406.87,901.61) 1(3421.08,1066.04) 1(3421.08,1073.95) 1(3421.08,1091.63) 1(3421.08,1099.54) 1(3421.08,1117.22) 1(3421.08,1125.13) 1(3421.08,1142.81) 1(3421.08,1150.72) 1(3421.49,1569.45) 1(3421.49,1597.04) 1(3421.49,1669.84) 1(3421.49,1697.44) 1(3424.63,773.62) 1(3424.63,801.21) 1(3424.63,874.01) 1(3424.63,901.61) 1(3440.8,1066.04) 1(3440.8,1073.95) 1(3440.8,1091.63) 1(3440.8,1099.54) 1(3440.8,1117.22) 1(3440.8,1125.13) 1(3440.8,1142.81) 1(3440.8,1150.72) 1(3441.14,1569.45) 1(3441.14,1597.04) 1(3441.14,1669.84) 1(3441.14,1697.44) 1(3458.9,1569.45) 1(3458.9,1597.04) 1(3458.9,1669.84) 1(3458.9,1697.44) 1(3478.54,1569.45) 1(3478.54,1597.04) 1(3478.54,1669.84) 1(3478.54,1697.44) 1(3496.3,1569.45) 1(3496.3,1597.04) 1(3496.3,1669.84) 1(3496.3,1697.44) 1(3531.32,1066.04) 1(3531.32,1073.95) 1(3531.32,1091.63) 1(3531.32,1099.54) 1(3531.32,1117.22) 1(3531.32,1125.13) 1(3531.32,1142.81) 1(3531.32,1150.72) 1(3551.04,1066.04) 1(3551.04,1073.95) 1(3551.04,1091.63) 1(3551.04,1099.54) 1(3551.04,1117.22) 1(3551.04,1125.13) 1(3551.04,1142.81) 1(3551.04,1150.72) 1(3664.65,2557.11) 1(3664.65,2574.86) 1(3664.65,2594.51) 1(3664.65,2612.26) 1(3664.65,2631.91) 1(3664.65,2649.66) 1(3692.25,2557.11) 1(3692.25,2574.86) 1(3692.25,2594.51) 1(3692.25,2612.26) 1(3692.25,2631.91) 1(3692.25,2649.66) 1(3765.05,2557.11) 1(3765.05,2574.86) 1(3765.05,2594.51) 1(3765.05,2612.26) 1(3765.05,2631.91) 1(3765.05,2649.66) 1(3792.64,2557.11) 1(3792.64,2574.86) 1(3792.64,2594.51) 1(3792.64,2612.26) 1(3792.64,2631.91) 1(3792.64,2649.66) 1(3835.34,1453.89) 1(3835.34,1461.81) 1(3835.34,1479.48) 1(3835.34,1487.4) 1(3835.34,1505.07) 1(3835.34,1512.99) 1(3849.16,1453.89) 1(3849.16,1461.81) 1(3849.16,1479.48) 1(3849.16,1487.4) 1(3849.16,1505.07) 1(3849.16,1512.99) 1(3912.11,1453.89) 1(3912.11,1461.81) 1(3912.11,1479.48) 1(3912.11,1487.4) 1(3912.11,1505.07) 1(3912.11,1512.99) 1(3925.93,1453.89) 1(3925.93,1461.81) 1(3925.93,1479.48) 1(3925.93,1487.4) 1(3925.93,1505.07) 1(3925.93,1512.99) 1(4041.03,2466.04) 1(4041.03,2473.96) 1(4041.03,2491.63) 1(4041.03,2499.55) 1(4041.03,2517.22) 1(4041.03,2525.14) 1(4041.03,2542.81) 1(4041.03,2550.73) 1(4060.75,2466.04) 1(4060.75,2473.96) 1(4060.75,2491.63) 1(4060.75,2499.55) 1(4060.75,2517.22) 1(4060.75,2525.14) 1(4060.75,2542.81) 1(4060.75,2550.73) 1(4151.27,2466.04) 1(4151.27,2473.96) 1(4151.27,2491.63) 1(4151.27,2499.55) 1(4151.27,2517.22) 1(4151.27,2525.14) 1(4151.27,2542.81) 1(4151.27,2550.73) 1(4170.99,2466.04) 1(4170.99,2473.96) 1(4170.99,2491.63) 1(4170.99,2499.55) 1(4170.99,2517.22) 1(4170.99,2525.14) 1(4170.99,2542.81) 1(4170.99,2550.73) 1(4335.08,1847.7) 1(4335.08,1870.18) 1(4335.08,1905.97) 1(4335.08,1928.45) 1(4343,1847.7) 1(4343,1870.18) 1(4343,1905.97) 1(4343,1928.45) 1(4354.77,1847.7) 1(4354.77,1870.18) 1(4354.77,1905.97) 1(4354.77,1928.45) 1(4362.68,1847.7) 1(4362.68,1870.18) 1(4362.68,1905.97) 1(4362.68,1928.45) 1(4374.45,1847.7) 1(4374.45,1870.18) 1(4374.45,1905.97) 1(4374.45,1928.45) 1(4382.37,1847.7) 1(4382.37,1870.18) 1(4382.37,1905.97) 1(4382.37,1928.45) 1(5105.67,2308.87) 1(5105.67,2371.9) 1(5121.42,2243.91) 1(5121.42,2275.44) 1(5121.42,2405.33) 1(5121.42,2436.86) 1(5123.42,2308.87) 1(5123.42,2371.9) 1(5156.89,2243.91) 1(5156.89,2275.44) 1(5156.89,2405.33) 1(5156.89,2436.86) 1(5184.41,2243.91) 1(5184.41,2275.44) 1(5184.41,2405.33) 1(5184.41,2436.86) 1(5219.88,2243.91) 1(5219.88,2275.44) 1(5219.88,2405.33) 1(5219.88,2436.86) 1(5363.67,1756.87) 1(5363.67,1819.9) 1(5379.42,1691.91) 1(5379.42,1723.44) 1(5379.42,1853.33) 1(5379.42,1884.86) 1(5381.42,1756.87) 1(5381.42,1819.9) 1(5414.89,1691.91) 1(5414.89,1723.44) 1(5414.89,1853.33) 1(5414.89,1884.86) 1(5442.41,1691.91) 1(5442.41,1723.44) 1(5442.41,1853.33) 1(5442.41,1884.86) 1(5477.88,1691.91) 1(5477.88,1723.44) 1(5477.88,1853.33) 1(5477.88,1884.86)
  round 80 on Mech16: 1(3601.66,4674.53)
  round 6 on Mech16: 1(3977.02,1042.44) 1(3977.02,1042.44) 1(3977.02,1266.44) 1(3977.02,1266.44) 1(4059.28,894.28) 1(4059.28,924.28) 1(4084.28,934.28) 1(4109.28,894.28) 1(4109.28,924.28) 1(4193.02,1042.44) 1(4193.02,1042.44) 1(4193.02,1266.44) 1(4193.02,1266.44) 1(4959.02,827.44) 1(4959.02,827.44) 1(4959.02,1051.44) 1(4959.02,1051.44) 1(5175.02,827.44) 1(5175.02,827.44) 1(5175.02,1051.44) 1(5175.02,1051.44)
  round 23.62 on Mech16: 1(4000.51,1352.66) 1(4000.51,1402.66) 1(4000.51,1452.66) 1(4000.51,1502.66) 1(4033.98,1352.66) 1(4033.98,1402.66) 1(4033.98,1452.66) 1(4033.98,1502.66) 1(4206.48,2947.39) 1(4215.08,1352.66) 1(4215.08,1402.66) 1(4215.08,1452.66) 1(4215.08,1502.66) 1(4230.1,2947.39) 1(4248.55,1352.66) 1(4248.55,1402.66) 1(4248.55,1452.66) 1(4248.55,1502.66)
  round 47.24 on Mech16: 1(4218.29,2947.39) 1(5368.65,710.59) 1(5368.65,848.39) 1(5368.65,986.18) 1(5368.65,1155.59) 1(5368.65,1293.39) 1(5368.65,1431.18)
  round 3.62 on Mech16: 1(4720.54,28.78) 1(4720.54,115.71) 1(4720.54,261.06) 1(4720.54,347.99) 1(4976.76,28.78) 1(4976.76,115.71) 1(4976.76,261.06) 1(4976.76,347.99)
  round 15.75 on Mech16: 1(5139.15,2222.28) 1(5397.15,1670.28)
  round 112 on Mech16: 1(5235.02,559.44)

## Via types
v1: diameter 18, hole 8, Top Layer to Bottom Layer, tented both sides, 832 vias
v2: diameter 19.68, hole 7.87, Top Layer to Bottom Layer, tented both sides, 34 vias
v3: diameter 17, hole 7.87, Top Layer to Bottom Layer, tented both sides, 1 vias
v4: diameter 17, hole 8, Top Layer to Bottom Layer, tented both sides, 1 vias

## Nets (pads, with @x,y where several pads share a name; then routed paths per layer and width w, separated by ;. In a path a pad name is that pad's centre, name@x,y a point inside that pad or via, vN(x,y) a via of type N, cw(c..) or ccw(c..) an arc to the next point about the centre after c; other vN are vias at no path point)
3V0: C7.1 C15.1 C16.1 C115.1 C116.1 C118.1 J4.6 J4.7 J6.6 J6.7 R79.2 R181.2 U4.5 U14.1 | length 3561.1
  Top Layer w10: J4.7@4653.44,4143.81 4671.13,4143.81 4681.23,4153.91 ; J4.6@4655.33,4163.49 4667.18,4163.49 4676.77,4153.91 4681.23,4153.91 ; v1(4774.17,4155.77) 4779.69,4155.77 4785.89,4149.58 C15.1@4785.89,4133.49 C16.1@4755.82,4133.49 4735.4,4153.91 4681.23,4153.91 ; J6.6@5721.75,3810.06 5721.75,3826.54 5731.98,3836.77 ; v1@5724.8,3872.26 5724.87,3872.2 C115.1@5754.85,3872.2 C116.1@5754.85,3843.74 5738.95,3843.74 5731.98,3836.77 ; J6.7@5741.43,3807.06 5741.43,3827.32 5731.98,3836.77 ; R181.2@6091.28,3842.57 6091.28,3904.1 6105.18,3918 6140.28,3918 6140.75,3918.46 6179.57,3918.46 6185.83,3924.73 v1(6188,3924.73)
  Sig1 w10: v1(6292.44,3789.79) 6292.44,3845.53 v1(6318.69,3871.77) 6219.2,3871.77 6188,3902.98 v1(6188,3924.73) 6312.25,3924.73 6361.98,3974.46 6595.15,3974.46 6706.81,3862.8 6706.81,3773.9 6715.61,3765.1 6715.61,3732.72 6729.54,3718.79 v1(6802.79,3718.79)
  PWR2 w10: v1(4774.17,4155.77) 4804.64,4186.24 4974.1,4186.24 5034.02,4126.32 5071.11,4126.32 5131.8,4187.02 5561.1,4187.02 5724.8,4023.32 v1@5724.8,3872.26
  Sig2 w10: v1@5724.8,3872.26 5771.52,3918.98 5880.99,3918.98 5897.71,3935.69 6050.18,3935.69 6066.07,3919.8 6175.26,3919.8 6178.66,3923.2
  Bottom Layer w10: U14.1@6272.54,3799.77 6272.54,3764.35 6272.5,3764.32 C118.1@6272.5,3743.88 6284.34,3743.88 6292.44,3751.98 v1(6292.44,3789.79) ; R79.2@6300.48,3856.48 6303.39,3856.48 v1(6318.69,3871.77) ; v1(6802.79,3718.79) 6804.79,3720.79 C7.1@6824.78,3720.79 6824.78,3743.97 6844.78,3763.97 U4.5@6844.78,3797.49
  other v1: 5724.6,3872.26
5V_HD_IN: C128.1 FL4.2 J2.2 R20.1 U19.8 | length 130.7
  Bottom Layer w6: J2.2@4816.76,3859.07 J2.2@4846.16,3859.07
  Bottom Layer w10: J2.2@4846.16,3859.07 J2.2@4882.13,3859.07 ; R20.1@6594.7,3988.94 6614.05,3988.94 6628.05,3974.95 v1(6628.05,3973.04)
  Bottom Layer w12: U19.8@6671.07,3812.08 U19.8@6676.3,3812.08 6695.37,3812.08
  other v1: 6660.22,3704.68 6688.14,3705.36 6652.66,3724.54 6673.29,3725.69 6695.37,3726.86 6651.3,3745.4 6671.76,3746.63 6693.22,3746.68 4884.01,3771.83 4880.03,3792.36 4896.01,3805.31 4879.68,3815.92 4897.7,3826.8 4881.21,3838.27 4904.62,3844.99 4926.63,3849.17 5605.92,4324.63 5581.03,4326.59 5630.7,4327.28 5606.6,4346.47 5587.7,4365.2 5626.58,4365.4
5V_IN: C1.2 C4.1 C30.1 C50.1 C51.1 C52.1 C53.1 D1.1 D2.1 FL3.2 FL12.2 R39.1 R50.2 R64.1 R107.1 U1.9 U1.13 U1.18 U1.22 U1.26 | length 1893
  Top Layer w8: U1.18@3116.84,4066.81 3116.84,4030.18 C30.1@3118.02,4029 3118.02,4009.5 v1(3120.52,4007) ; v1@4551.43,3756.69 4551.24,3756.88 D2.1@4578.64,3756.88
  Top Layer w10: R39.1@2654.65,4222.86 2655.01,4222.86 2655.01,4236.01 2739.16,4320.16 R50.2@2823.15,4320.16 ; C51.1@2981.75,4092.11 3004.16,4092.11 3014.29,4102.24 U1.13@3046.37,4102.24 ; C50.1@2981.75,4191.11 3004.16,4191.11 3014.29,4180.98 U1.9@3046.37,4180.98 ; v1(3024.1,3939.47) 3024.3,3939.67 C1.2@3024.3,3970.8 ; U1.22@3167.63,4102.24 3199.71,4102.24 3209.84,4092.11 C52.1@3232.25,4092.11 ; U1.26@3167.63,4180.98 3199.71,4180.98 3209.84,4191.11 C53.1@3232.25,4191.11 ; R107.1@4962.66,4484.7 4978.83,4484.7 v1(4989.81,4473.72)
  Top Layer w15: v1(3241.75,4236.41) 3242.57,4235.59 3242.57,4215.73 v1(3243.4,4214.9) ; FL12.2@5975.6,4292.41 5999,4292.41 v1(6133.65,4427.06)
  Top Layer w20: FL3.2@6670.79,3888.25 6665.81,3893.23 6665.81,3926.17 v3(6709.55,3969.91)
  PWR2 w20: v1(6133.65,4427.06) 6139.35,4432.76 6167.96,4432.76 6227.55,4373.17 6227.55,4293.13 6292.2,4228.49 6433.98,4228.49 6466.25,4196.22 6592.78,4196.22 6714.81,4074.19 6714.81,3975.17 v3(6709.55,3969.91)
  Bottom Layer w10: R64.1@3715.38,4092.76 3723.59,4092.76 v1(3736.09,4105.26)
  other v1: 4578.79,3691.57 4538.61,3702.12 4561.98,3704.97 4546.15,3719.86 4575.02,3723.05 4554.85,3738.64 4535.84,3740.59 4545.8,3759.4 3224.8,4068.32 3243.5,4068.32 2970.43,4068.82 2988.61,4068.82 2970,4214.35 2988.35,4214.35 3224.9,4214.9 2797.98,4277.53 2818.98,4277.53 2797.98,4298.58 2818.98,4298.58
5V_IN_B: C42.2 C122.1 C127.1 FL14.2 TP4.1 U19.6
  other v1: 6741.2,4058 6741.81,4081.54 6764.6,4082.97 6741.81,4103 6765.01,4106.67 6741.32,4124.11 6764.46,4130
5V_IN_SW: C129.1 FL11.1 R27.1 U19.7 | length 465.6
  Top Layer w6: v1@4691.08,3733.43 FL11.1@4691.08,3755.5
  PWR1 w10: v1(6606.39,3717.68) 6645.55,3678.52 6731.31,3678.52 6805.46,3752.67
  Bottom Layer w10: v1(6606.39,3717.68) R27.1@6606.39,3741.52 ; U19.7@6673.76,3836.69 6698.11,3836.69 6703.21,3831.6 ; 6711.81,3839.4 6710.11,3841.1 ; 6726.91,3841.1 6710.11,3841.1 ; 6740.73,3819.94 6729.08,3831.6 6703.21,3831.6 ; 6703.21,3831.6 6673.82,3831.6 6671.83,3835.22 6669.11,3840.2 6670.01,3841.1 6710.11,3841.1
  other v1: 4714.24,3699.46 4733.54,3699.67 4691.05,3701.13 4705.46,3716.04 4725.75,3716.89 4693.16,3730.65 4713.56,3733.58 4731.02,3739.71 6757.93,3742.77 6782.31,3747.33 4742.06,3755.27 6756.77,3763.83 6779.56,3766.42 6798.43,3774.05 6750.69,3781.76 6770.14,3787.01 6788.19,3794.02
ALERT: R38.1 U5.3 U10.4 | length 362.8
  Top Layer w5.5: v1(5298.45,4304.31) 5298.66,4304.11 5388.73,4304.11 v1(5388.94,4303.9)
  Bottom Layer w5.5: U5.3@5271.66,4192.9 5271.83,4193.07 5271.83,4228.81 R38.1@5272,4228.98 5272,4229.76 5278.42,4236.19 5281.51,4236.19 5287.43,4242.1 5287.43,4291.9 5298.45,4302.93 v1(5298.45,4304.31) ; U10.4@5338.3,4426.11 5346.17,4426.11 5388.94,4383.34 v1(5388.94,4303.9)
AR_1P0_RF1: C78.1 C79.1 C80.1 C81.1 C124.1 C137.1 C139.1 L12.2 U2.J16 U2.J17 U2.J18 | length 66.8
  Top Layer w10: U2.J16@4040.73,4346.33 v1(4056.48,4362.08) ; U2.J17@4040.73,4377.83 v1(4056.48,4393.58) ; U2.J18@4040.73,4409.33 v1(4056.48,4425.07)
  other v1: 4070.23,4284.1 4092.37,4284.1 4120.07,4284.1 4085.43,4303.88 4121.16,4303.88 2921.96,4369.31 2951.08,4369.31 2921.31,4393.27 2950.43,4393.27
AR_1P0_RF2: C70.1 C73.1 C74.1 C75.1 C76.1 C82.1 C83.1 C84.1 C85.1 C131.1 C132.1 C140.1 L14.2 L15.2 U2.G16 U2.G17 U2.G18 U2.H16 U2.H17 U2.H18 | length 133.6
  Top Layer w10: v1(3961.99,4362.08) U2.G16@3977.74,4346.33 ; v1(3961.99,4393.58) U2.G17@3977.74,4377.83 ; v1(3961.99,4425.07) U2.G18@3977.74,4409.33 ; v1(3993.49,4362.08) U2.H16@4009.24,4346.33 ; v1(3993.49,4393.58) U2.H17@4009.24,4377.83 ; v1(3993.49,4425.07) U2.H18@4009.24,4409.33
  other v1: 3916.06,4284.1 3938.08,4284.1 3958.01,4284.1 3941.08,4308.95 3963.26,4308.95 3987.33,4308.95 3504.24,4317.15 3524.61,4317.15 3544.99,4317.15 3504.24,4337.53 3524.61,4337.53 3544.99,4337.53 3524.61,4357.9 3544.99,4357.9
AR_1P2: C91.1 C92.1 C94.1 C95.1 C96.1 C97.1 C98.1 C103.1 C133.1 C134.1 C141.1 L13.2 U2.A5 U2.C1 U2.E1 U2.J1 U2.V4 U2.V6 U2.V7 U2.V8 U2.V12 U2.V14 U2.V15 | length 669.1
  Top Layer w10: U2.A5@3788.76,3999.88 v1(3804.51,4015.63) ; v1(3836.01,3858.15) U2.C1@3851.76,3873.89 ; v1(3899,3858.15) U2.E1@3914.75,3873.89 ; U2.J1@4040.84,3873.78 v1(4056.59,3858.04) ; v1(4308.45,3984.13) U2.V4@4324.2,3968.38 ; U2.V6@4324.2,4031.37 v1@4339.94,4015.63 ; U2.V7@4324.2,4062.87 4324.2,4065.87 v1(4341.94,4083.62) 4339.55,4086.01 4335.33,4086.01 4326.97,4094.37 U2.V8@4324.2,4094.37 ; U2.V12@4324.2,4220.35 4335.73,4231.88 4362.85,4231.88 4370,4224.73 C96.1@4388.37,4224.73 4388.37,4205.15 v1(4390.55,4202.96) 4368.37,4202.96 v1(4367.19,4204.15) ; U2.V14@4324.2,4283.34 4324.2,4285.59 4338.42,4285.59 4352,4299.17 ; U2.V15@4324.2,4314.84 4336.34,4314.84 4352,4299.17 ; v1(4397.76,4343.62) 4389.31,4335.17 v1(4378,4335.17) 4388.37,4324.81 C98.1@4388.37,4308.78 4361.61,4308.78 4352,4299.17
  Bottom Layer w10: C97.1@3779.79,4039.17 3803.34,4015.63 v1(3804.51,4015.63) ; v1(3899,3858.15) 3899.78,3858.15 C95.1@3922.37,3880.73 ; v1(4056.59,3858.04) 4056.59,3863.94 C92.1@4065.74,3873.08 ; C91.1@4303,4035.17 4321.4,4035.17 v1(4340.94,4015.63) ; C103.1@4303,4058.8 4317.13,4058.8 v1(4341.94,4083.62) ; C94.1@4304.21,3964.68 4304.21,3979.89 v1(4308.45,3984.13)
  other v1: 3049.61,3852.97 3075.1,3852.97 3022.75,3853.56 3023.03,3880.43 3049.9,3879.84 3075.69,3879.84
AR_1V4_APLL: C90.1 U2.A10 | length 62.3
  Top Layer w10: C90.1@3737.06,4182.85 3763.27,4182.85 U2.A10@3788.76,4157.36
AR_1V4_SYNTH: C89.1 U2.A9 | length 55.5
  Top Layer w10: C89.1@3737.19,4135.45 3779.18,4135.45 U2.A9@3788.76,4125.86
AR_1V8: C55.1 C56.1 C57.1 C58.1 C59.1 C60.1 C61.1 C62.1 C63.1 C64.1 C65.1 C66.1 C67.1 C68.1 C135.1 C136.1 C138.1 L11.2 U2.A12 U2.B1 U2.C11 U2.C15 U2.C18 U2.F1 U2.K1 U2.M16 U2.M17 U2.M18 U2.U2 U2.V11 | length 1964.3
  Top Layer w5.5: 4309.57,3888.52 4340.79,3888.52
  Top Layer w10: C63.1@3737.19,4215.47 3759.7,4215.47 v1(3764,4211.16) 3779.58,4211.16 U2.A12@3788.76,4220.35 ; v1(3804.51,3858.15) U2.B1@3820.26,3873.89 ; v1(3836.01,4299.09) U2.C15@3851.76,4314.84 ; U2.C11@3851.76,4188.85 v1(3867.5,4173.11) ; U2.C18@3851.76,4409.33 v1(3867.5,4393.58) ; v1(3930.5,3858.15) U2.F1@3946.24,3873.89 ; U2.K1@4072.23,3873.89 v1(4087.98,3858.15) ; U2.M16@4135.22,4346.33 v1(4150.97,4362.08) U2.M17@4135.22,4377.83 v1(4150.97,4393.58) ; U2.M18@4135.22,4409.33 v1(4150.97,4425.07) ; v1(4276.95,3921.14) U2.U2@4292.7,3905.39 4309.57,3888.52 ; v1(4308.45,4173.11) U2.V11@4324.2,4188.85 ; 4340.79,3888.52 4346.63,3882.68 C60.1@4378.33,3882.68
  Sig1 w7: v1(3930.5,3858.15) 4031.74,3858.15 4048.7,3875.1 4071.02,3875.1 v1(4087.98,3858.15)
  Sig1 w10: 3530.95,4025.34 3530.95,4066.7 3581.25,4117 3638.45,4117 3680.33,4158.88 3680.33,4168.07 3723.42,4211.16 v1(3764,4211.16) 3764,4163.79 3776.3,4151.49 3814.59,4151.49 3836.2,4173.11 v1(3867.5,4173.11) ; v1(4087.98,3992.71) 4087.98,4113.34 4093.74,4119.11 4195.18,4119.11 4244.54,4168.46 4303.81,4168.46 v1(4308.45,4173.11)
  Sig2 w10: v1(3867.5,4393.58) 3849.3,4375.38 3849.3,4312.39 v1(3836.01,4299.09) 3877.1,4299.09 3919.6,4341.59 4130.47,4341.59 v1(4150.97,4362.08)
  Bottom Layer w5.5: C61.1@4282,4185.3 4292.87,4185.3 4305.07,4173.11 v1(4308.45,4173.11)
  Bottom Layer w10: v1(3867.5,4393.58) 3873.35,4399.42 C68.1@3873.35,4409.24 ; C65.1@3891,4188 C65.1@3891,4192.68
  other v1: 3451.04,3940.81 3496.94,3970.86 3451.17,4008.69 3496.94,4008.69
AR_BSS_LOGGER: RA2.2 U2.D3 | length 1186.6
  Top Layer w5.5: U2.D3@3883.25,3936.89 v1(3899,3952.63) ; RA2.2@4588.48,4434.82 4588.48,4456.94 4602.74,4471.2 v1(4620,4471.2)
  Sig1 w4.2: v1(3899,3952.63) 3917.29,3970.92 3979.16,3970.92 4021.78,4013.55 4021.78,4178.81 4043.81,4200.84 4165.64,4200.84 4186.78,4221.98 4230.31,4221.98 4244.52,4236.19 4409.44,4236.19 4419.12,4245.88 4517.88,4245.88 4620,4348 v1(4620,4471.2)
AR_CS1: R9.2 R139.2 U2.C2 | length 3686.1
  Top Layer w5.5: v1(3836.01,3889.64) U2.C2@3851.76,3905.39 ; v1(6715.81,4184) 6803.81,4184 6824.81,4205 R139.2@6824.81,4242.98
  Sig2 w4.2: v1(3836.01,3889.64) 3877.36,3889.64 3892.66,3904.94 3922.93,3904.94 3957.26,3870.61 4030.19,3870.61 4046.16,3886.58 4060.81,3886.58 4079.18,3904.94 4328.02,3904.94 4364.57,3868.39 4514.72,3868.39 4539.2,3843.9 4570.88,3843.9 4600.01,3814.77 4600.01,3792.88 4617.82,3775.07 4669.7,3775.07 4765.52,3870.89 4864.06,3870.89 4877.53,3884.36 4945.71,3884.36 4960.32,3898.97 5084.46,3898.97 5095.62,3910.13 5191.61,3910.13 5250.87,3850.87 5250.87,3817.75 5364.49,3704.13 5714.75,3704.13 5717.21,3706.59 ; 5717.23,3706.58 5756.47,3745.82 5805.57,3745.82 5852.75,3698.64 6113.4,3698.64 6261.73,3846.97 6327.4,3846.97 6378.67,3898.24 6456.83,3898.24 6495.24,3936.65 6653.69,3936.65 6705.11,3988.08 6705.11,4122.6 6715.63,4133.12 6715.63,4183.82 v1(6715.81,4184)
  Bottom Layer w5.5: R9.2@3835,3909.17 3835,3890.65 v1(3836.01,3889.64)
AR_CS1_60PIN: R150.2 RA3.1 U11.3 | length 2822.8
  Top Layer w5.5: RA3.1@4749.31,3863.01 4739.81,3853.51 4739.81,3789.61 4813.32,3716.09 4860.31,3716.09 4868.31,3724.09 4868.31,3760.6 4862.91,3766 4862.91,3883.01 ; U11.3@4886.95,3921.94 4874.63,3921.94 4862.91,3910.21 4862.91,3883.01 ; v1(4906.85,3901) 4880.9,3901 4862.91,3883.01
  Bottom Layer w5.5: v1(4906.85,3901) 4928.03,3879.82 5087.82,3879.82 5129.04,3838.6 5129.04,3799.06 5148.22,3779.88 5148.22,3745.94 5190.88,3703.29 5619.79,3703.29 5631.01,3714.5 5631.01,4077.45 5550.4,4158.05 5550.4,4408.54 5698.22,4556.36 5832.98,4556.36 5897.02,4492.31 6056.57,4492.31 6109.13,4439.75 6109.13,4421.75 6126.41,4404.47 R150.2@6126.41,4381.76
AR_CS1_BT: R105.2 U8.30 | length 1804.6
  Top Layer w4: v1(6074.75,3981.21) 6092.1,3981.21 6110.01,3963.3 6145.73,3963.3 6150.97,3968.54 6181.35,3968.54 6220.41,3929.48 6313.22,3929.48 6333.54,3949.8 U8.30@6333.54,3977.25
  Top Layer w5.5: R105.2@4865.78,4005.59 4937.34,4005.59 4966.51,4034.75 4979.48,4034.75 5001.05,4056.32 5117.17,4056.32 5147.18,4026.31 5147.18,4024.17 5230.5,3940.85 5289.82,3940.85 v1(5338.37,3892.31)
  Sig1 w4.2: v1(5338.37,3892.31) 5470.47,3760.2 5484.36,3760.2 5531.15,3713.41 5686.42,3713.41 5764.29,3791.28 5870.55,3791.28 6050.3,3971.03 ; 6050.39,3970.94 6060.67,3981.21 v1(6074.75,3981.21)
